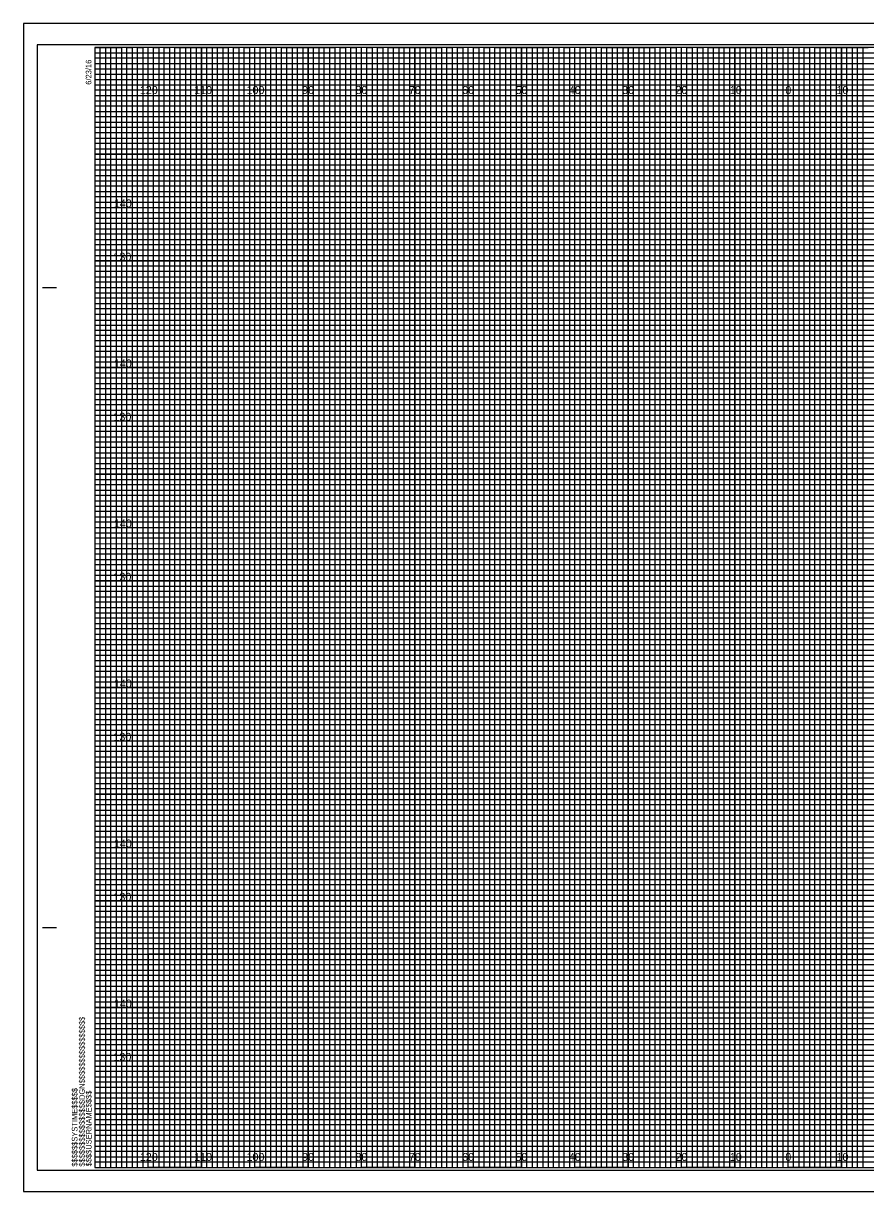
# Model space of a CAD drawing. Extents: x -13 to 323, y -5 to 3294.
# Drawn here: x -13.4 to 144.5, y 1755.5 to 1974.5 of the extents above; entities that cross this region are included whole.
import ezdxf

# ---------------------------------------------------------------- set-up
doc = ezdxf.new("R2010")
doc.units = 0
for name, color, linetype in [('Prop XS Elevation Labels', 7, 'Continuous'), ('Prop XS Offset Labels', 7, 'Continuous'), ('Scratch_Level_0', 7, 'Continuous'), ('Sheet Cross Section CELL', 7, 'Continuous'), ('Sheet Cross Section Grid Major CELL', 7, 'Continuous'), ('Sheet Cross Section Grid Middle CELL', 7, 'Continuous'), ('Sheet Cross Section Grid Minor 1 CELL', 7, 'Continuous'), ('Sheet Cross Section Grid Minor 2 CELL', 7, 'Continuous'), ('Sheet Cutting Line CELL', 7, 'Continuous'), ('Sheet DOT Grid CELL', 7, 'Continuous'), ('Sheet Plot Border Inside CELL', 7, 'Continuous'), ('Sheet Plot Border Outside CELL', 7, 'Continuous')]:
    doc.layers.add(name, color=color, linetype=linetype)

msp = doc.modelspace()

# ---------------------------------------------------------------- linework, layer by layer
at = {"layer": 'Scratch_Level_0'}
msp.add_lwpolyline([(310, 1800), (10, 1800), (10, 1770), (310, 1770)], close=True, dxfattribs=at)
at = {"layer": 'Sheet Cross Section CELL'}
for p, q in [((-9.8, 1925), (-7.3, 1925)), ((-9.7, 1925), (-7.2, 1925)), ((-9.8, 1805), (-7.3, 1805)), ((-9.7, 1805), (-7.2, 1805)), ((0, 1760), (0, 1760)), ((0, 1760), (0, 1760)), ((0, 1760), (0, 1760)), ((0, 1760), (0, 1760)), ((0, 1760), (0, 1760)), ((0, 1760), (0, 1760)), ((0, 1760), (0, 1760))]:
    msp.add_line(p, q, dxfattribs=at)
msp.add_lwpolyline([(320, 1970), (0, 1970), (0, 1760), (320, 1760)], close=True, dxfattribs=at)
at = {"layer": 'Sheet Cross Section Grid Major CELL'}
for p, q in [((10, 1970), (0, 1970)), ((10, 1760), (10, 1970)), ((30, 1970), (20, 1970)), ((20, 1970), (20, 1760)), ((30, 1760), (30, 1970)), ((50, 1970), (40, 1970)), ((40, 1970), (40, 1760)), ((50, 1760), (50, 1970)), ((70, 1970), (60, 1970)), ((60, 1970), (60, 1760)), ((70, 1760), (70, 1970)), ((90, 1970), (80, 1970)), ((80, 1970), (80, 1760)), ((90, 1760), (90, 1970)), ((110, 1970), (100, 1970)), ((100, 1970), (100, 1760)), ((110, 1760), (110, 1970)), ((130, 1970), (120, 1970)), ((120, 1970), (120, 1760)), ((130, 1760), (130, 1970)), ((150, 1970), (140, 1970)), ((140, 1970), (140, 1760)), ((20, 1760), (10, 1760)), ((40, 1760), (30, 1760)), ((60, 1760), (50, 1760)), ((80, 1760), (70, 1760)), ((100, 1760), (90, 1760)), ((120, 1760), (110, 1760)), ((140, 1760), (130, 1760))]:
    msp.add_line(p, q, dxfattribs=at)
for points in [[(0, 1960), (320, 1960), (320, 1950), (0, 1950)], [(0, 1940), (320, 1940), (320, 1930), (0, 1930)], [(0, 1920), (320, 1920), (320, 1910), (0, 1910)], [(0, 1900), (320, 1900), (320, 1890), (0, 1890)], [(0, 1880), (320, 1880), (320, 1870), (0, 1870)], [(0, 1860), (320, 1860), (320, 1850), (0, 1850)], [(0, 1840), (320, 1840), (320, 1830), (0, 1830)], [(0, 1820), (320, 1820), (320, 1810), (0, 1810)], [(0, 1800), (320, 1800), (320, 1790), (0, 1790)], [(0, 1780), (320, 1780), (320, 1770), (0, 1770)]]:
    msp.add_lwpolyline(points, dxfattribs=at)
at = {"layer": 'Sheet Cross Section Grid Middle CELL'}
for points in [[(0, 1970), (5, 1970), (5, 1760), (15, 1760), (15, 1970), (25, 1970), (25, 1760), (35, 1760), (35, 1970), (45, 1970), (45, 1760), (55, 1760), (55, 1970), (65, 1970), (65, 1760), (75, 1760), (75, 1970), (85, 1970), (85, 1760), (95, 1760), (95, 1970), (105, 1970), (105, 1760), (115, 1760), (115, 1970), (125, 1970), (125, 1760), (135, 1760), (135, 1970), (145, 1970)], [(0, 1965), (275, 1965)], [(0, 1945), (320, 1945), (320, 1955), (0, 1955)], [(0, 1925), (320, 1925), (320, 1935), (0, 1935)], [(0, 1905), (320, 1905), (320, 1915), (0, 1915)], [(0, 1885), (320, 1885), (320, 1895), (0, 1895)], [(0, 1865), (320, 1865), (320, 1875), (0, 1875)], [(0, 1845), (320, 1845), (320, 1855), (0, 1855)], [(0, 1825), (320, 1825), (320, 1835), (0, 1835)], [(0, 1805), (320, 1805), (320, 1815), (0, 1815)], [(0, 1785), (320, 1785), (320, 1795), (0, 1795)], [(0, 1765), (320, 1765), (320, 1775), (0, 1775)]]:
    msp.add_lwpolyline(points, dxfattribs=at)
at = {"layer": 'Sheet Cross Section Grid Minor 1 CELL'}
for p, q in [((0, 1969), (260, 1969)), ((260, 1967.98), (0, 1967.98)), ((0, 1967.98), (0, 1967)), ((0, 1967), (260, 1967)), ((260, 1965.89), (0, 1965.89)), ((0, 1965.89), (0, 1964)), ((0, 1964), (320, 1964))]:
    msp.add_line(p, q, dxfattribs=at)
for points in [[(0, 1963), (270, 1963), (320, 1963), (320, 1962), (0, 1962)], [(0, 1961), (320, 1961), (320, 1959), (0, 1959)], [(0, 1958), (320, 1958), (320, 1957), (0, 1956.98)], [(0, 1956), (320, 1956), (320, 1954), (0, 1954)], [(0, 1953), (320, 1953), (320, 1952), (0, 1952)], [(0, 1951), (320, 1951), (320, 1949), (0, 1949)], [(0, 1948), (320, 1948), (320, 1947), (0, 1947)], [(0, 1946), (320, 1946), (320, 1944), (0, 1944)], [(0, 1943), (320, 1943), (320, 1942), (0, 1942)], [(0, 1941), (320, 1941), (320, 1939), (0, 1939)], [(0, 1938), (320, 1938), (320, 1937), (0, 1937)], [(0, 1936), (320, 1936), (320, 1933.95), (320, 1933), (320, 1932), (0, 1932)], [(0, 1934), (320, 1934), (320, 1933), (0, 1933)], [(0, 1931), (320, 1931), (320, 1929), (0, 1929.03)], [(0, 1929.03), (320, 1929), (320, 1928), (0, 1928)], [(0, 1927), (320, 1927), (320, 1926), (0, 1926)], [(0, 1924), (320, 1924), (320, 1923), (0, 1923)], [(0, 1922), (320, 1922), (320, 1921), (0, 1921)], [(-0.07, 1918.89), (320, 1918.89), (320, 1917.88), (-0.07, 1917.88)], [(0, 1917), (320, 1917), (320, 1916), (0, 1916)], [(0, 1914), (320, 1914), (320, 1913), (0, 1913)], [(0, 1912), (320, 1912), (320, 1911), (0, 1911)], [(0, 1909), (320, 1909), (320, 1908), (0, 1908)], [(0, 1907), (320, 1907), (320, 1906), (0, 1906)], [(0, 1904), (320, 1904), (320, 1903), (0, 1903)], [(0, 1902), (320, 1902), (320, 1901), (0, 1901)], [(0, 1899), (320, 1899), (319.99, 1897.98), (0, 1898)], [(0, 1897), (320, 1897), (320, 1896), (0, 1896)], [(0, 1894), (320, 1894), (320, 1893), (0, 1893)], [(0, 1892), (320, 1892), (320, 1891), (0, 1891)], [(0, 1889), (320, 1889), (320, 1888), (0, 1888)], [(0, 1887), (320, 1887), (320, 1886), (0, 1886)], [(0, 1884), (320, 1884), (320, 1883), (0, 1883)], [(0, 1882), (320, 1882), (320, 1881), (0, 1881)], [(0, 1879), (320, 1879), (320, 1878), (0, 1878)], [(0, 1876.99), (320.07, 1876.91), (320, 1876), (0, 1876)], [(0, 1874), (320, 1874), (320, 1873), (0, 1873)], [(0, 1872), (320, 1872), (320, 1871), (0, 1871)], [(0, 1869), (320, 1869), (320, 1868), (0, 1868)], [(0, 1867), (320, 1867), (320, 1866), (0, 1866)], [(0, 1864), (320, 1864), (320, 1863), (0, 1863)], [(0, 1862), (320, 1862), (320, 1861), (0, 1861)], [(0, 1859), (320, 1859), (320, 1858), (0, 1858)], [(0, 1857), (320, 1857), (320, 1856), (0, 1856)], [(0, 1854), (320, 1854), (320, 1853), (0, 1853)], [(0, 1852), (320, 1852), (320, 1851), (0, 1851)], [(0, 1849), (320, 1849), (320, 1848), (0, 1848)], [(0, 1847), (320, 1847), (320, 1846), (0, 1846)], [(0, 1844), (320, 1844), (320, 1843), (0, 1843)], [(0, 1842), (320, 1842), (320, 1841), (0, 1841)], [(0, 1839), (320, 1839), (319.99, 1837.98), (0, 1838)], [(0, 1837), (320, 1837), (320, 1836), (0, 1836)], [(0, 1834), (320, 1834), (320, 1833), (0, 1833)], [(0, 1832), (320, 1832), (320, 1831), (0, 1831)], [(0, 1829), (320, 1829), (320, 1828), (0, 1828)], [(0, 1827), (320, 1827), (320, 1826), (0, 1826)], [(0, 1824), (320, 1824), (320, 1823), (0, 1823)], [(0, 1822), (320, 1822), (320, 1821), (0, 1821)], [(0, 1819), (320, 1819), (320, 1818), (0, 1818)], [(0, 1816.99), (320.07, 1816.91), (320, 1816), (0, 1816)], [(0, 1814), (320, 1814), (320, 1813), (0, 1813)], [(0, 1812), (320, 1812), (320, 1811), (0, 1811)], [(0, 1809), (320, 1809), (320, 1808), (0, 1808)], [(0, 1807), (320, 1807), (320, 1806), (0, 1806)], [(0, 1804), (320, 1804), (320, 1803), (0, 1803)], [(0, 1802), (320, 1802), (320, 1801), (0, 1801)], [(0, 1799), (320, 1799), (320, 1798), (0, 1798)], [(0, 1797), (320, 1797), (320, 1796), (0, 1796)], [(0, 1794), (320, 1794), (320, 1793), (0, 1793)], [(0, 1792), (320, 1792), (320, 1791), (0, 1791)], [(0, 1789), (320, 1789), (320, 1788), (0, 1788)], [(0, 1787), (320, 1787), (320, 1786), (0, 1786)], [(0, 1784), (320, 1784), (320, 1783), (0, 1783)], [(0, 1782), (320, 1782), (320, 1781), (0, 1781)], [(0, 1779), (320, 1779), (320, 1778), (0, 1778)], [(0, 1777), (320, 1777), (320, 1776), (0, 1776)], [(0, 1774), (320, 1774), (320, 1773), (0, 1773)], [(0, 1772), (320, 1772), (320, 1771), (0, 1771)], [(0, 1769), (320, 1769), (320, 1768), (0, 1768)], [(0, 1767), (320, 1767), (320, 1766), (0, 1766)], [(0, 1764), (320, 1764), (320, 1763), (0, 1763)], [(0, 1762), (320, 1762), (320, 1761), (0, 1761)]]:
    msp.add_lwpolyline(points, dxfattribs=at)
at = {"layer": 'Sheet Cross Section Grid Minor 2 CELL'}
for points in [[(0, 1760), (1, 1760), (1, 1970), (2, 1970), (2, 1760)], [(2, 1760), (3, 1760), (3, 1970), (4, 1970), (4, 1760)], [(5, 1760), (6, 1760), (6, 1970), (7, 1970), (7, 1760)], [(7, 1760), (8, 1760), (8, 1970), (9, 1970), (9, 1760)], [(10, 1760), (11, 1760), (11, 1970), (12, 1970), (12, 1760)], [(12, 1760), (13, 1760), (13, 1970), (14, 1970), (14, 1760)], [(15, 1760), (16, 1760), (16, 1970), (17, 1970), (17, 1760)], [(17, 1760), (18, 1760), (18, 1970), (19, 1970), (19, 1760)], [(20, 1760), (21, 1760), (21, 1970), (22, 1970), (22, 1760)], [(22, 1760), (23, 1760), (23, 1970), (24, 1970), (24, 1760)], [(25, 1760), (26, 1760), (26, 1970), (27, 1970), (27, 1760)], [(27, 1760), (28, 1760), (28, 1970), (29, 1970), (29, 1760)], [(30, 1760), (31, 1760), (31, 1970), (32, 1970), (32, 1760)], [(32, 1760), (33, 1760), (33, 1970), (34, 1970), (34, 1760)], [(35, 1760), (36, 1760), (36, 1970), (37, 1970), (37, 1760)], [(37, 1760), (38, 1760), (38, 1970), (39, 1970), (39, 1760)], [(40, 1760), (41, 1760), (41, 1970), (42, 1970), (42, 1760)], [(42, 1760), (43, 1760), (43, 1970), (44, 1970), (44, 1760)], [(45, 1760), (46, 1760), (46, 1970), (47, 1970), (47, 1760)], [(47, 1760), (48, 1760), (48, 1970), (49, 1970), (49, 1760)], [(50, 1760), (51, 1760), (51, 1970), (52, 1970), (52, 1760)], [(52, 1760), (53, 1760), (53, 1970), (54, 1970), (54, 1760)], [(55, 1760), (56, 1760), (56, 1970), (57, 1970), (57, 1760)], [(57, 1760), (58, 1760), (58, 1970), (59, 1970), (59, 1760)], [(60, 1760), (61, 1760), (61, 1970), (62, 1970), (62, 1760)], [(62, 1760), (63, 1760), (63, 1970), (64, 1970), (64, 1760)], [(65, 1760), (66, 1760), (66, 1970), (67, 1970), (67, 1760)], [(67, 1760), (68, 1760), (68, 1970), (69, 1970), (69, 1760)], [(70, 1760), (71, 1760), (71, 1970), (72, 1970), (72, 1760)], [(72, 1760), (73, 1760), (73, 1970), (74, 1970), (74, 1760)], [(75, 1760), (76, 1760), (76, 1970), (77, 1970), (77, 1760)], [(77, 1760), (78, 1760), (78, 1970), (79, 1970), (79, 1760)], [(80, 1760), (81, 1760), (81, 1970), (82, 1970), (82, 1760)], [(82, 1760), (83, 1760), (83, 1970), (84, 1970), (84, 1760)], [(85, 1760), (86, 1760), (86, 1970), (87, 1970), (87, 1760)], [(87, 1760), (88, 1760), (88, 1970), (89, 1970), (89, 1760)], [(90, 1760), (91, 1760), (91, 1970), (92, 1970), (92, 1760)], [(92, 1760), (93, 1760), (93, 1970), (94, 1970), (94, 1760)], [(95, 1760), (96, 1760), (96, 1970), (97, 1970), (97, 1760)], [(97, 1760), (98, 1760), (98, 1970), (99, 1970), (99, 1760)], [(100, 1760), (101, 1760), (101, 1970), (102, 1970), (102, 1760)], [(102, 1760), (103, 1760), (103, 1970), (104, 1970), (104, 1760)], [(105, 1760), (106, 1760), (106, 1970), (107, 1970), (107, 1760)], [(107, 1760), (108, 1760), (108, 1970), (109, 1970), (109, 1760)], [(110, 1760), (111, 1760), (111, 1970), (112, 1970), (112, 1760)], [(112, 1760), (113, 1760), (113, 1970), (114, 1970), (114, 1760)], [(115, 1760), (116, 1760), (116, 1970), (117, 1970), (117, 1760)], [(117, 1760), (118, 1760), (118, 1970), (119, 1970), (119, 1760)], [(120, 1760), (121, 1760), (121, 1970), (122, 1970), (122, 1760)], [(122, 1760), (123, 1760), (123, 1970), (124, 1970), (124, 1760)], [(125, 1760), (126, 1760), (126, 1970), (127, 1970), (127, 1760)], [(127, 1760), (128, 1760), (128, 1970), (129, 1970), (129, 1760)], [(130, 1760), (131, 1760), (131, 1970), (132, 1970), (132, 1760)], [(132, 1760), (133, 1760), (133, 1970), (134, 1970), (134, 1760)], [(135, 1760), (136, 1760), (136, 1970), (137, 1970), (137, 1760)], [(137, 1760), (138, 1760), (138, 1970), (139, 1970), (139, 1760)], [(140, 1760), (141, 1760), (141, 1970), (142, 1970), (142, 1760)], [(142, 1760), (143, 1760), (143, 1970), (144, 1970), (144, 1760)]]:
    msp.add_lwpolyline(points, dxfattribs=at)
at = {"layer": 'Sheet Cutting Line CELL'}
for p, q in [((323.3, 1974.5), (-13.4, 1974.5)), ((-13.4, 1974.5), (-13.4, 1755.5)), ((-13.4, 1755.5), (323.3, 1755.5))]:
    msp.add_line(p, q, dxfattribs=at)
at = {"layer": 'Sheet DOT Grid CELL'}
for p, q in [((10, 1760), (10, 1970)), ((20, 1760), (20, 1970)), ((30, 1760), (30, 1970)), ((40, 1760), (40, 1970)), ((50, 1760), (50, 1970)), ((60, 1760), (60, 1970)), ((70, 1760), (70, 1970)), ((80, 1760), (80, 1970)), ((90, 1760), (90, 1970)), ((100, 1760), (100, 1970)), ((110, 1760), (110, 1970)), ((120, 1760), (120, 1970)), ((130, 1760), (130, 1970)), ((140, 1760), (140, 1970)), ((0, 1960), (320, 1960)), ((0, 1950), (320, 1950)), ((0, 1940), (320, 1940)), ((0, 1930), (320, 1930)), ((0, 1920), (320, 1920)), ((0, 1910), (320, 1910)), ((0, 1900), (320, 1900)), ((0, 1890), (320, 1890)), ((0, 1880), (320, 1880)), ((0, 1870), (320, 1870)), ((0, 1860), (320, 1860)), ((0, 1850), (320, 1850)), ((0, 1840), (320, 1840)), ((0, 1830), (320, 1830)), ((0, 1820), (320, 1820)), ((0, 1810), (320, 1810)), ((0, 1800), (320, 1800)), ((0, 1790), (320, 1790)), ((0, 1780), (320, 1780)), ((0, 1770), (320, 1770))]:
    msp.add_line(p, q, dxfattribs=at)
at = {"layer": 'Sheet Plot Border Inside CELL'}
msp.add_lwpolyline([(-10.8, 1759.5), (322.4, 1759.5), (322.4, 1970.5), (-10.8, 1970.5)], close=True, dxfattribs=at)
at = {"layer": 'Sheet Plot Border Outside CELL'}
msp.add_lwpolyline([(-13.4, 1755.5), (323.3, 1755.5), (323.3, 1974.5), (-13.4, 1974.5)], close=True, dxfattribs=at)

# ---------------------------------------------------------------- texts
at = {"layer": 'Prop XS Elevation Labels'}
for s, p in [('140', (3.57, 1940)), ('130', (3.49, 1930)), ('140', (3.57, 1910)), ('130', (3.49, 1900)), ('140', (3.57, 1880)), ('130', (3.49, 1870)), ('140', (3.57, 1850)), ('130', (3.49, 1840)), ('140', (3.57, 1820)), ('130', (3.49, 1810)), ('140', (3.57, 1790)), ('130', (3.49, 1780))]:
    msp.add_text(s, height=1.5, dxfattribs=at).set_placement(p)
at = {"layer": 'Prop XS Offset Labels'}
for s, p in [('120', (8.44, 1961.25)), ('110', (18.62, 1961.25)), ('100', (28.44, 1961.25)), ('90', (38.86, 1961.25)), ('80', (48.86, 1961.25)), ('70', (58.86, 1961.25)), ('60', (68.86, 1961.25)), ('50', (78.86, 1961.25)), ('40', (88.86, 1961.25)), ('30', (98.86, 1961.25)), ('20', (108.86, 1961.25)), ('10', (119.04, 1961.25)), ('0', (129.45, 1961.25)), ('0', (129.45, 1961.25)), ('10', (139.04, 1961.25)), ('120', (8.44, 1761.25)), ('110', (18.62, 1761.25)), ('100', (28.44, 1761.25)), ('90', (38.86, 1761.25)), ('80', (48.86, 1761.25)), ('70', (58.86, 1761.25)), ('60', (68.86, 1761.25)), ('50', (78.86, 1761.25)), ('40', (88.86, 1761.25)), ('30', (98.86, 1761.25)), ('20', (108.86, 1761.25)), ('10', (119.04, 1761.25)), ('0', (129.45, 1761.25)), ('0', (129.45, 1761.25)), ('10', (139.04, 1761.25))]:
    msp.add_text(s, height=1.5, dxfattribs=at).set_placement(p)
at = {"layer": 'Sheet Cross Section CELL'}
for s, p in [('6/23/16', (-0.65, 1963)), ('$$$$$$$$$$$$$$$$DGN$$$$$$$$$$$$$$$$', (-1.88, 1760.18)), ('$$$$$$SYSTIME$$$$$', (-3.26, 1760.18)), ('$$$$USERNAME$$$$', (-0.62, 1760.23))]:
    msp.add_text(s, height=1.05, rotation=90, dxfattribs=at).set_placement(p)

doc.saveas('drawing.dxf')
